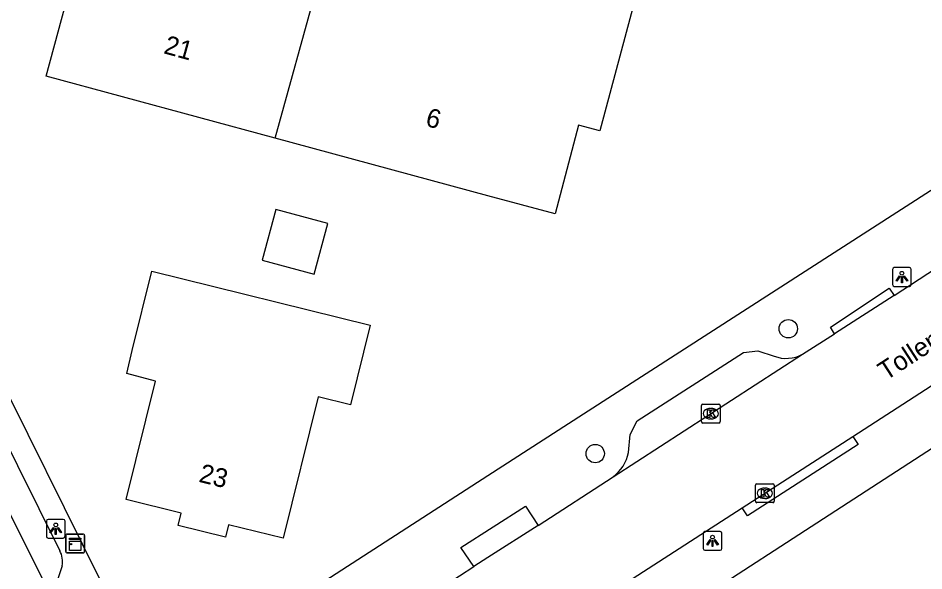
# Model space of a CAD drawing. Extents: x 161354 to 161876, y 382161 to 382804.
# Drawn here: x 161474.99 to 161523.22, y 382412.84 to 382442.26 of the extents above; entities that cross this region are included whole.
import ezdxf

# ---------------------------------------------------------------- set-up
doc = ezdxf.new("R2010")
doc.units = 0
for name, color, linetype in [('IMGEO_Boom', 7, 'Continuous'), ('IMGEO_Kast', 7, 'Continuous'), ('IMGEO_Kolk', 7, 'Continuous'), ('IMGEO_Lichtpunt', 7, 'Continuous'), ('IMGEO_Openbare_ruimte_label', 7, 'Continuous'), ('IMGEO_Pand', 7, 'Continuous'), ('IMGEO_Pand_nummerreeks', 7, 'Continuous'), ('IMGEO_Rijbaan_lokaal_open', 7, 'Continuous'), ('IMGEO_Voetpad_open', 7, 'Continuous')]:
    doc.layers.add(name, color=color, linetype=linetype)

msp = doc.modelspace()

# ---------------------------------------------------------------- linework, layer by layer
at = {"layer": 'IMGEO_Boom'}
for centre in [(161515.996, 382425.728), (161505.717, 382419.085)]:
    msp.add_circle(centre, 0.489, dxfattribs=at)
at = {"layer": 'IMGEO_Kast'}
for p, q in [((161477.528, 382413.877), (161477.528, 382414.718)), ((161477.528, 382414.718), (161477.528, 382413.877)), ((161477.603, 382414.802), (161478.444, 382414.802)), ((161478.444, 382414.802), (161477.603, 382414.802)), ((161478.528, 382414.727), (161478.528, 382413.886)), ((161478.528, 382413.886), (161478.528, 382414.727)), ((161478.453, 382413.802), (161477.612, 382413.802)), ((161477.612, 382413.802), (161478.453, 382413.802))]:
    msp.add_line(p, q, dxfattribs=at)
for points in [[(161477.723, 382414.592), (161478.323, 382414.592), (161478.323, 382414.507), (161477.723, 382414.507), (161477.723, 382414.592)], [(161477.723, 382414.417), (161478.323, 382414.417), (161478.323, 382413.928), (161477.723, 382413.928), (161477.723, 382414.417)]]:
    msp.add_lwpolyline(points, dxfattribs=at)
msp.add_circle((161477.807, 382414.266), 0.0377, dxfattribs=at)
for centre, start, end in [((161477.606, 382414.724), 92.4484, 184.2845), ((161477.606, 382414.724), 92.4484, 184.2845), ((161478.45, 382414.724), 2.4484, 94.2845), ((161478.45, 382414.724), 2.4484, 94.2845), ((161477.606, 382413.88), 182.4484, 274.2845), ((161477.606, 382413.88), 182.4484, 274.2845), ((161478.45, 382413.88), 272.4484, 4.2845), ((161478.45, 382413.88), 272.4484, 4.2845)]:
    msp.add_arc(centre, 0.0779, start, end, dxfattribs=at)
at = {"layer": 'IMGEO_Kolk'}
for p, q in [((161511.373, 382420.784), (161511.373, 382421.636)), ((161511.448, 382421.71), (161512.3, 382421.71)), ((161511.861, 382421.49), (161511.886, 382421.49)), ((161512.374, 382421.636), (161512.374, 382420.784)), ((161511.884, 382420.93), (161511.859, 382420.93)), ((161512.3, 382420.71), (161511.448, 382420.71)), ((161514.247, 382416.547), (161514.247, 382417.399)), ((161514.322, 382417.473), (161515.174, 382417.473)), ((161514.735, 382417.253), (161514.76, 382417.253)), ((161515.248, 382417.399), (161515.248, 382416.547)), ((161514.758, 382416.693), (161514.733, 382416.693)), ((161515.174, 382416.473), (161514.322, 382416.473))]:
    msp.add_line(p, q, dxfattribs=at)
for points in [[(161511.373, 382420.784), (161511.373, 382421.636)], [(161511.448, 382421.71), (161512.3, 382421.71)], [(161511.694, 382421.41), (161511.817, 382421.41), (161511.817, 382421.259), (161511.947, 382421.41), (161512.111, 382421.41), (161511.965, 382421.259), (161512.118, 382421.01), (161511.966, 382421.01), (161511.881, 382421.174), (161511.817, 382421.107), (161511.817, 382421.01), (161511.694, 382421.01), (161511.694, 382421.41)], [(161512.374, 382421.636), (161512.374, 382420.784)], [(161512.3, 382420.71), (161511.448, 382420.71)], [(161514.247, 382416.547), (161514.247, 382417.399)], [(161514.322, 382417.473), (161515.174, 382417.473)], [(161514.568, 382417.173), (161514.691, 382417.173), (161514.691, 382417.022), (161514.821, 382417.173), (161514.985, 382417.173), (161514.839, 382417.022), (161514.992, 382416.773), (161514.84, 382416.773), (161514.755, 382416.937), (161514.691, 382416.87), (161514.691, 382416.773), (161514.568, 382416.773), (161514.568, 382417.173)], [(161515.248, 382417.399), (161515.248, 382416.547)], [(161515.174, 382416.473), (161514.322, 382416.473)]]:
    msp.add_lwpolyline(points, dxfattribs=at)
for centre, start, end in [((161511.45, 382421.634), 91.552, 178.448), ((161511.45, 382421.634), 91.552, 178.448), ((161512.298, 382421.634), 1.552, 88.448), ((161512.298, 382421.634), 1.552, 88.448), ((161511.45, 382420.786), 181.552, 268.448), ((161511.45, 382420.786), 181.552, 268.448), ((161512.298, 382420.786), 271.552, 358.448), ((161512.298, 382420.786), 271.552, 358.448), ((161514.324, 382417.397), 91.552, 178.448), ((161514.324, 382417.397), 91.552, 178.448), ((161515.172, 382417.397), 1.552, 88.448), ((161515.172, 382417.397), 1.552, 88.448), ((161514.324, 382416.549), 181.552, 268.448), ((161514.324, 382416.549), 181.552, 268.448), ((161515.172, 382416.549), 271.552, 358.448), ((161515.172, 382416.549), 271.552, 358.448)]:
    msp.add_arc(centre, 0.0765, start, end, dxfattribs=at)
for centre, major_axis, ratio, start_param, end_param in [((161511.86, 382421.21), (-0.387, 0.002), 0.722429, 4.712389, 7.853982), ((161511.885, 382421.21), (-0.39, 0.002), 0.717154, 1.570796, 4.712389), ((161514.734, 382416.973), (-0.387, 0.002), 0.722429, 4.712389, 7.853982), ((161514.759, 382416.973), (-0.39, 0.002), 0.717154, 1.570796, 4.712389)]:
    msp.add_ellipse(centre, major_axis=major_axis, ratio=ratio, start_param=start_param, end_param=end_param, dxfattribs=at)
at = {"layer": 'IMGEO_Lichtpunt'}
for p, q in [((161521.547, 382428.885), (161521.547, 382428.078)), ((161521.547, 382428.885), (161521.547, 382428.078)), ((161522.449, 382428.98), (161521.641, 382428.98)), ((161522.449, 382428.98), (161521.641, 382428.98)), ((161522.543, 382428.078), (161522.543, 382428.885)), ((161522.543, 382428.078), (161522.543, 382428.885)), ((161521.641, 382427.984), (161522.449, 382427.984)), ((161521.641, 382427.984), (161522.449, 382427.984)), ((161477.397, 382415.582), (161476.589, 382415.582)), ((161477.397, 382415.582), (161476.589, 382415.582)), ((161476.495, 382415.487), (161476.495, 382414.68)), ((161476.495, 382415.487), (161476.495, 382414.68)), ((161477.491, 382414.68), (161477.491, 382415.487)), ((161477.491, 382414.68), (161477.491, 382415.487)), ((161511.465, 382414.841), (161511.465, 382414.034)), ((161511.465, 382414.841), (161511.465, 382414.034)), ((161512.367, 382414.936), (161511.559, 382414.936)), ((161512.367, 382414.936), (161511.559, 382414.936)), ((161512.461, 382414.034), (161512.461, 382414.841)), ((161512.461, 382414.034), (161512.461, 382414.841)), ((161476.589, 382414.586), (161477.397, 382414.586)), ((161476.589, 382414.586), (161477.397, 382414.586)), ((161511.559, 382413.94), (161512.367, 382413.94)), ((161511.559, 382413.94), (161512.367, 382413.94))]:
    msp.add_line(p, q, dxfattribs=at)
for points in [[(161521.921, 382428.549), (161521.96, 382428.521), (161521.772, 382428.259), (161521.734, 382428.286), (161521.921, 382428.549)], [(161522.023, 382428.501), (161522.07, 382428.501), (161522.07, 382428.179), (161522.023, 382428.179), (161522.023, 382428.501)], [(161522.133, 382428.521), (161522.171, 382428.548), (161522.358, 382428.286), (161522.319, 382428.258), (161522.133, 382428.521)], [(161476.869, 382415.151), (161476.908, 382415.123), (161476.72, 382414.861), (161476.682, 382414.888), (161476.869, 382415.151)], [(161476.971, 382415.103), (161477.018, 382415.103), (161477.018, 382414.781), (161476.971, 382414.781), (161476.971, 382415.103)], [(161477.081, 382415.123), (161477.119, 382415.15), (161477.306, 382414.888), (161477.267, 382414.86), (161477.081, 382415.123)], [(161511.839, 382414.505), (161511.878, 382414.477), (161511.69, 382414.215), (161511.652, 382414.242), (161511.839, 382414.505)], [(161511.941, 382414.457), (161511.988, 382414.457), (161511.988, 382414.135), (161511.941, 382414.135), (161511.941, 382414.457)], [(161512.051, 382414.477), (161512.089, 382414.504), (161512.276, 382414.242), (161512.237, 382414.214), (161512.051, 382414.477)]]:
    msp.add_lwpolyline(points, dxfattribs=at)
for centre in [(161522.046, 382428.683), (161476.994, 382415.285), (161511.964, 382414.639)]:
    msp.add_circle(centre, 0.0994, dxfattribs=at)
for centre, start, end in [((161521.641, 382428.885), 90, 180), ((161521.641, 382428.885), 90, 180), ((161522.449, 382428.885), 0, 90), ((161522.449, 382428.885), 0, 90), ((161521.641, 382428.078), 180, 270), ((161521.641, 382428.078), 180, 270), ((161522.449, 382428.078), 270, 0), ((161522.449, 382428.078), 270, 360), ((161476.589, 382415.487), 90, 180), ((161476.589, 382415.487), 90, 180), ((161477.397, 382415.487), 0, 90), ((161477.397, 382415.487), 0, 90), ((161476.589, 382414.68), 180, 270), ((161476.589, 382414.68), 180, 270), ((161477.397, 382414.68), 270, 0), ((161477.397, 382414.68), 270, 360), ((161511.559, 382414.841), 90, 180), ((161511.559, 382414.841), 90, 180), ((161512.367, 382414.841), 0, 90), ((161512.367, 382414.841), 0, 90), ((161511.559, 382414.034), 180, 270), ((161511.559, 382414.034), 180, 270), ((161512.367, 382414.034), 270, 0), ((161512.367, 382414.034), 270, 360)]:
    msp.add_arc(centre, 0.0946, start, end, dxfattribs=at)
at = {"layer": 'IMGEO_Pand'}
for points in [[(161488.68, 382435.875), (161476.487, 382439.176), (161477.768, 382443.906), (161476.63, 382444.215), (161478.858, 382452.439), (161484.457, 382450.923), (161484.884, 382452.497), (161495.536, 382449.613)], [(161495.536, 382449.613), (161500, 382448.404), (161503.021, 382447.586), (161502.593, 382446.004), (161508.161, 382444.488), (161505.955, 382436.264), (161504.826, 382436.559), (161503.582, 382431.84), (161500, 382432.81), (161488.68, 382435.875)], [(161488.68, 382435.875), (161490.891, 382443.899), (161493.745, 382443.112), (161495.536, 382449.613)], [(161487.988, 382429.383), (161490.76, 382428.633), (161491.488, 382431.322), (161488.716, 382432.072), (161487.988, 382429.383)], [(161493.742, 382425.925), (161492.692, 382421.673), (161490.964, 382422.1), (161489.105, 382414.576), (161486.188, 382415.297), (161486.025, 382414.636), (161483.506, 382415.258), (161483.669, 382415.919), (161480.752, 382416.639), (161482.308, 382422.939), (161480.785, 382423.343), (161481.07, 382424.579), (161482.112, 382428.798), (161493.742, 382425.925)]]:
    msp.add_lwpolyline(points, dxfattribs=at)
at = {"layer": 'IMGEO_Rijbaan_lokaal_open'}
for points in [[(161477.113, 382410.786), (161463.455, 382438.086)], [(161521.629, 382427.501), (161526.95, 382430.969), (161527.109, 382431.082)], [(161521.629, 382427.501), (161518.456, 382425.465)], [(161519.44, 382419.989), (161530.443, 382427.111)], [(161516.756, 382424.376), (161518.456, 382425.465)], [(161506.665, 382417.849), (161516.756, 382424.376)], [(161513.549, 382416.2), (161519.44, 382419.989)], [(161502.672, 382415.264), (161506.665, 382417.849)], [(161501.881, 382408.673), (161513.549, 382416.2)], [(161502.672, 382415.264), (161500, 382413.556), (161499.259, 382413.082)], [(161496.079, 382411.013), (161496.209, 382411.097), (161499.259, 382413.082)]]:
    msp.add_lwpolyline(points, dxfattribs=at)
at = {"layer": 'IMGEO_Voetpad_open'}
for points in [[(161559.394, 382456.082), (161542.283, 382445.088), (161532.279, 382438.666), (161505.088, 382421.185), (161500, 382417.897), (161486.459, 382409.147), (161486.172, 382408.962), (161485.951, 382409.016), (161480.33, 382410.398)], [(161572.419, 382451.387), (161564.764, 382446.042), (161558.459, 382441.915), (161500, 382404.037), (161487.478, 382395.924)], [(161480.33, 382410.398), (161464.946, 382441.398)], [(161464.352, 382437.542), (161465.51, 382437.074), (161465.956, 382436.55), (161477.208, 382413.913)], [(161518.456, 382425.465), (161518.25, 382425.816), (161521.37, 382427.891), (161521.629, 382427.501)], [(161507.486, 382419.143), (161507.572, 382420.093), (161507.958, 382420.823), (161513.617, 382424.465), (161514.378, 382424.56), (161515.248, 382424.271)], [(161519.44, 382419.989), (161519.71, 382419.569), (161513.819, 382415.78), (161513.549, 382416.2)], [(161499.259, 382413.082), (161498.571, 382414.091), (161502.007, 382416.279), (161502.672, 382415.264)], [(161477.329, 382413.106), (161477.068, 382412.309)]]:
    msp.add_lwpolyline(points, dxfattribs=at)
for centre, radius, start, end in [((161515.89, 382425.926), 1.775, 248.786, 299.18), ((161505.483, 382419.507), 2.036, 305.5007, 349.7117), ((161476.243, 382413.356), 1.115, 347.0554, 29.9992)]:
    msp.add_arc(centre, radius, start, end, dxfattribs=at)

# ---------------------------------------------------------------- texts
at = {"layer": 'IMGEO_Openbare_ruimte_label'}
msp.add_text('Tollenslaan', height=1, rotation=32.959, dxfattribs=at).set_placement((161521.193, 382422.944))
at = {"layer": 'IMGEO_Pand_nummerreeks'}
for s, rotation, p in [('21', 344.5964, (161482.694, 382440.397)), ('6', 344.4821, (161496.627, 382436.542)), ('23', 346.123, (161484.568, 382417.591))]:
    msp.add_text(s, height=1, rotation=rotation, dxfattribs=at).set_placement(p)

doc.saveas('drawing.dxf')
